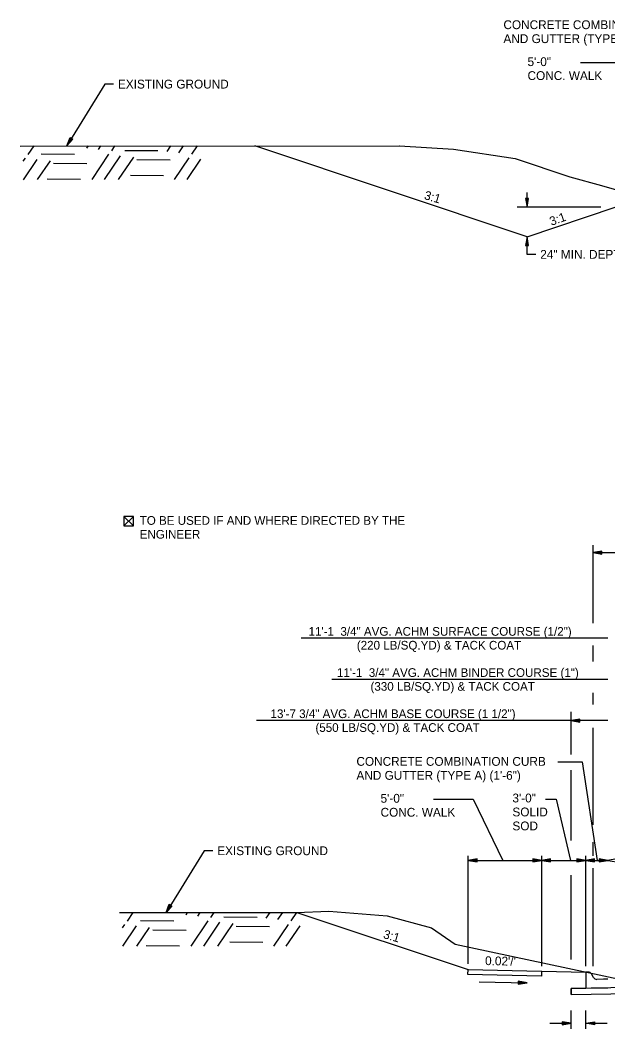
# Model space of a CAD drawing. Extents: x 1001270 to 1003428, y 1840152 to 1842912.
# Drawn here: x 1001270.4 to 1001310.4, y 1842116.6 to 1842185.2 of the extents above; entities that cross this region are included whole.
import ezdxf

# ---------------------------------------------------------------- set-up
doc = ezdxf.new("R2010")
doc.units = 0
for name, color, linetype in [('10', 7, 'Continuous'), ('19', 7, 'Continuous'), ('20', 7, 'Continuous'), ('8', 7, 'Continuous'), ('Default', 7, 'Continuous')]:
    doc.layers.add(name, color=color, linetype=linetype)

# ---------------------------------------------------------------- blocks, each defined once
blk = doc.blocks.new('TM')
at = {"layer": '8'}
for p, q in [((-120.309, 21.181), (-119.787, -20.829)), ((0, 0), (-120.309, 21.181)), ((-31.382, 2.945), (-120.176, 10.512)), ((-119.787, -20.829), (0, 0)), ((-119.911, -10.826), (-31.307, -3.057))]:
    blk.add_line(p, q, dxfattribs=at)

msp = doc.modelspace()

# ---------------------------------------------------------------- linework, layer by layer
at = {"layer": '10'}
for p, q in [((1001277.481, 1842151.422), (1001278.123, 1842150.781)), ((1001278.123, 1842151.422), (1001277.481, 1842150.781)), ((1001277.863, 1842150.781), (1001277.874, 1842150.781))]:
    msp.add_line(p, q, dxfattribs=at)
msp.add_lwpolyline([(1001277.874, 1842150.781), (1001278.123, 1842150.781), (1001278.123, 1842151.422), (1001277.481, 1842151.422), (1001277.481, 1842150.781), (1001277.863, 1842150.781)], dxfattribs=at)
at = {"layer": '19'}
for p, q in [((1001308.535, 1842182.289), (1001311.246, 1842182.289)), ((1001273.593, 1842176.626), (1001273.817, 1842177.193)), ((1001273.667, 1842176.767), (1001273.86, 1842177.16)), ((1001273.817, 1842177.193), (1001273.995, 1842177.083)), ((1001270.971, 1842176.041), (1001271.363, 1842176.624)), ((1001273.995, 1842177.083), (1001273.593, 1842176.626)), ((1001273.954, 1842177.104), (1001273.69, 1842176.755)), ((1001274.957, 1842176.475), (1001275.062, 1842176.625)), ((1001275.751, 1842176.383), (1001275.917, 1842176.627)), ((1001276.647, 1842176.291), (1001276.872, 1842176.63)), ((1001280.411, 1842176.235), (1001280.673, 1842176.631)), ((1001281.205, 1842176.144), (1001281.537, 1842176.632)), ((1001282.101, 1842176.051), (1001282.482, 1842176.625)), ((1001304.904, 1842170.448), (1001286.377, 1842176.624)), ((1001270.632, 1842175.573), (1001270.785, 1842175.798)), ((1001271.86, 1842176.08), (1001274.12, 1842176.059)), ((1001275.309, 1842174.328), (1001276.461, 1842176.049)), ((1001276.163, 1842174.33), (1001277.256, 1842175.957)), ((1001277.119, 1842174.332), (1001278.151, 1842175.865)), ((1001277.534, 1842176.32), (1001279.795, 1842176.309)), ((1001280.919, 1842174.333), (1001281.915, 1842175.809)), ((1001270.654, 1842174.324), (1001271.58, 1842175.707)), ((1001271.609, 1842174.326), (1001272.475, 1842175.615)), ((1001272.7, 1842175.451), (1001274.96, 1842175.429)), ((1001278.364, 1842175.692), (1001280.635, 1842175.68)), ((1001281.773, 1842174.336), (1001282.71, 1842175.717)), ((1001277.922, 1842174.622), (1001280.182, 1842174.6)), ((1001272.247, 1842174.371), (1001274.518, 1842174.359)), ((1001305.009, 1842173.048), (1001304.799, 1842173.048)), ((1001304.799, 1842173.048), (1001304.904, 1842172.448)), ((1001304.849, 1842173.048), (1001304.889, 1842172.608)), ((1001304.904, 1842172.448), (1001304.904, 1842173.451)), ((1001304.904, 1842172.448), (1001305.009, 1842173.048)), ((1001304.919, 1842172.608), (1001304.954, 1842173.048)), ((1001309.914, 1842172.448), (1001304.234, 1842172.448)), ((1001304.904, 1842170.448), (1001310.902, 1842172.448)), ((1001304.904, 1842170.448), (1001304.799, 1842169.848)), ((1001305.009, 1842169.848), (1001304.904, 1842170.448)), ((1001304.904, 1842169.242), (1001304.904, 1842170.448)), ((1001304.799, 1842169.848), (1001305.009, 1842169.848)), ((1001304.889, 1842170.288), (1001304.854, 1842169.848)), ((1001304.959, 1842169.848), (1001304.919, 1842170.288)), ((1001305.504, 1842169.242), (1001304.904, 1842169.242)), ((1001309.401, 1842144.149), (1001309.401, 1842149.464)), ((1001310.001, 1842149.066), (1001309.401, 1842148.961)), ((1001310.001, 1842148.856), (1001310.001, 1842149.066)), ((1001309.401, 1842148.961), (1001375.401, 1842148.961)), ((1001309.401, 1842148.961), (1001310.001, 1842148.856)), ((1001310.001, 1842149.011), (1001309.561, 1842148.976)), ((1001309.561, 1842148.946), (1001310.001, 1842148.906)), ((1001310.407, 1842143.127), (1001289.535, 1842143.127)), ((1001309.401, 1842141.54), (1001309.401, 1842142.648)), ((1001310.401, 1842140.328), (1001291.623, 1842140.328)), ((1001309.401, 1842138.634), (1001309.401, 1842139.415)), ((1001307.901, 1842135.23), (1001307.901, 1842138.128)), ((1001310.401, 1842137.528), (1001286.495, 1842137.528)), ((1001308.501, 1842137.633), (1001307.901, 1842137.528)), ((1001307.901, 1842137.528), (1001308.501, 1842137.423)), ((1001308.501, 1842137.578), (1001308.061, 1842137.543)), ((1001308.061, 1842137.513), (1001308.501, 1842137.473)), ((1001308.501, 1842137.423), (1001308.501, 1842137.633)), ((1001309.401, 1842130.45), (1001309.401, 1842137.03)), ((1001306.992, 1842134.716), (1001308.66, 1842134.716)), ((1001308.66, 1842134.716), (1001309.675, 1842128.024)), ((1001307.901, 1842129.372), (1001307.901, 1842134.158)), ((1001298.536, 1842132.181), (1001301.247, 1842132.181)), ((1001301.247, 1842132.181), (1001303.26, 1842128.01)), ((1001306.152, 1842132.181), (1001306.896, 1842132.181)), ((1001306.896, 1842132.181), (1001307.852, 1842128.024)), ((1001309.401, 1842128.335), (1001309.401, 1842129.264)), ((1001300.901, 1842120.976), (1001300.901, 1842128.324)), ((1001301.501, 1842128.129), (1001300.901, 1842128.024)), ((1001300.901, 1842128.024), (1001310.401, 1842128.024)), ((1001300.901, 1842128.024), (1001301.501, 1842127.919)), ((1001301.501, 1842128.074), (1001301.061, 1842128.039)), ((1001301.061, 1842128.009), (1001301.501, 1842127.969)), ((1001301.501, 1842127.919), (1001301.501, 1842128.129)), ((1001305.301, 1842128.129), (1001305.301, 1842127.919)), ((1001305.901, 1842128.024), (1001305.301, 1842128.129)), ((1001305.741, 1842128.039), (1001305.301, 1842128.074)), ((1001305.301, 1842127.919), (1001305.901, 1842128.024)), ((1001305.301, 1842127.969), (1001305.741, 1842128.009)), ((1001305.901, 1842120.823), (1001305.901, 1842128.324)), ((1001306.501, 1842128.129), (1001305.901, 1842128.024)), ((1001305.901, 1842128.024), (1001306.501, 1842127.919)), ((1001306.501, 1842128.074), (1001306.061, 1842128.039)), ((1001306.061, 1842128.009), (1001306.501, 1842127.969)), ((1001306.501, 1842127.919), (1001306.501, 1842128.129)), ((1001308.301, 1842128.129), (1001308.301, 1842127.919)), ((1001308.901, 1842128.024), (1001308.301, 1842128.129)), ((1001308.741, 1842128.039), (1001308.301, 1842128.074)), ((1001308.301, 1842127.919), (1001308.901, 1842128.024)), ((1001308.301, 1842127.969), (1001308.741, 1842128.009)), ((1001308.901, 1842120.823), (1001308.901, 1842128.324)), ((1001309.501, 1842128.129), (1001308.901, 1842128.024)), ((1001308.901, 1842128.024), (1001309.501, 1842127.919)), ((1001309.501, 1842128.074), (1001309.061, 1842128.039)), ((1001309.061, 1842128.009), (1001309.501, 1842127.969)), ((1001309.501, 1842127.919), (1001309.501, 1842128.129)), ((1001309.801, 1842128.129), (1001309.801, 1842127.919)), ((1001310.401, 1842128.024), (1001309.801, 1842128.129)), ((1001310.241, 1842128.039), (1001309.801, 1842128.074)), ((1001309.801, 1842127.919), (1001310.401, 1842128.024)), ((1001309.801, 1842127.969), (1001310.241, 1842128.009)), ((1001311.001, 1842128.129), (1001310.401, 1842128.024)), ((1001310.401, 1842128.024), (1001311.001, 1842127.919)), ((1001309.401, 1842120.826), (1001309.401, 1842127.504)), ((1001307.901, 1842121.289), (1001307.901, 1842127.028)), ((1001280.345, 1842124.48), (1001280.568, 1842125.047)), ((1001280.419, 1842124.621), (1001280.611, 1842125.015)), ((1001280.568, 1842125.047), (1001280.746, 1842124.937)), ((1001277.723, 1842123.895), (1001278.114, 1842124.478)), ((1001280.746, 1842124.937), (1001280.345, 1842124.48)), ((1001280.705, 1842124.959), (1001280.441, 1842124.61)), ((1001281.708, 1842124.329), (1001281.814, 1842124.479)), ((1001282.503, 1842124.237), (1001282.669, 1842124.482)), ((1001283.398, 1842124.145), (1001283.624, 1842124.484)), ((1001287.162, 1842124.09), (1001287.424, 1842124.485)), ((1001287.957, 1842123.998), (1001288.289, 1842124.486)), ((1001288.852, 1842123.906), (1001289.233, 1842124.48)), ((1001277.383, 1842123.427), (1001277.537, 1842123.653)), ((1001278.611, 1842123.934), (1001280.871, 1842123.913)), ((1001282.06, 1842122.182), (1001283.212, 1842123.903)), ((1001282.915, 1842122.185), (1001284.007, 1842123.811)), ((1001283.87, 1842122.187), (1001284.902, 1842123.719)), ((1001284.286, 1842124.175), (1001286.546, 1842124.163)), ((1001287.67, 1842122.188), (1001288.666, 1842123.664)), ((1001277.405, 1842122.179), (1001278.332, 1842123.561)), ((1001278.36, 1842122.181), (1001279.227, 1842123.469)), ((1001279.451, 1842123.305), (1001281.711, 1842123.284)), ((1001285.116, 1842123.546), (1001287.386, 1842123.534)), ((1001288.525, 1842122.19), (1001289.461, 1842123.572)), ((1001284.674, 1842122.476), (1001286.933, 1842122.455)), ((1001278.998, 1842122.226), (1001281.269, 1842122.213)), ((1001300.887, 1842120.258), (1001300.901, 1842120.591)), ((1001305.886, 1842120.157), (1001300.887, 1842120.258)), ((1001300.901, 1842120.591), (1001305.899, 1842120.49)), ((1001305.899, 1842120.49), (1001305.886, 1842120.157)), ((1001309.067, 1842120.43), (1001308.901, 1842120.43)), ((1001308.901, 1842120.43), (1001308.901, 1842120.097)), ((1001309.429, 1842120.055), (1001309.283, 1842120.306)), ((1001305.886, 1842120.157), (1001305.886, 1842120.157)), ((1001308.901, 1842120.097), (1001308.901, 1842119.915)), ((1001308.901, 1842119.915), (1001308.901, 1842119.322)), ((1001310.116, 1842119.939), (1001309.651, 1842119.93)), ((1001310.401, 1842119.945), (1001310.116, 1842119.939)), ((1001310.116, 1842119.939), (1001310.116, 1842119.939)), ((1001310.116, 1842119.939), (1001310.116, 1842119.939)), ((1001316.396, 1842119.482), (1001307.901, 1842119.302)), ((1001307.901, 1842119.302), (1001308.901, 1842119.322)), ((1001307.901, 1842118.895), (1001307.901, 1842119.302)), ((1001307.901, 1842119.302), (1001307.901, 1842118.895)), ((1001307.901, 1842118.895), (1001323.401, 1842119.205)), ((1001307.901, 1842118.895), (1001323.401, 1842119.205)), ((1001308.901, 1842119.322), (1001310.401, 1842119.353)), ((1001307.901, 1842116.566), (1001307.901, 1842117.804)), ((1001308.901, 1842116.566), (1001308.901, 1842117.804)), ((1001306.452, 1842116.944), (1001307.901, 1842116.944)), ((1001306.452, 1842116.944), (1001307.901, 1842116.944)), ((1001307.301, 1842117.049), (1001307.301, 1842116.839)), ((1001307.901, 1842116.944), (1001307.301, 1842117.049)), ((1001307.301, 1842117.049), (1001307.301, 1842116.839)), ((1001307.901, 1842116.944), (1001307.301, 1842117.049)), ((1001307.741, 1842116.959), (1001307.301, 1842116.994)), ((1001307.741, 1842116.959), (1001307.301, 1842116.994)), ((1001307.301, 1842116.839), (1001307.901, 1842116.944)), ((1001307.301, 1842116.839), (1001307.901, 1842116.944)), ((1001307.301, 1842116.889), (1001307.741, 1842116.929)), ((1001307.301, 1842116.889), (1001307.741, 1842116.929)), ((1001308.901, 1842116.944), (1001309.501, 1842117.049)), ((1001308.901, 1842116.944), (1001309.501, 1842117.049)), ((1001309.501, 1842116.839), (1001308.901, 1842116.944)), ((1001308.901, 1842116.944), (1001310.349, 1842116.944)), ((1001309.501, 1842116.839), (1001308.901, 1842116.944)), ((1001308.901, 1842116.944), (1001310.349, 1842116.944)), ((1001309.061, 1842116.959), (1001309.501, 1842116.994)), ((1001309.061, 1842116.959), (1001309.501, 1842116.994)), ((1001309.501, 1842116.889), (1001309.061, 1842116.929)), ((1001309.501, 1842116.889), (1001309.061, 1842116.929)), ((1001309.501, 1842117.049), (1001309.501, 1842116.839)), ((1001309.501, 1842117.049), (1001309.501, 1842116.839))]:
    msp.add_line(p, q, dxfattribs=at)
for points in [[(1001276.776, 1842180.825), (1001276.176, 1842180.825), (1001273.593, 1842176.626)], [(1001270.422, 1842176.607), (1001296.261, 1842176.634)], [(1001296.221, 1842176.634), (1001299.91, 1842176.411), (1001304.093, 1842175.76), (1001307.815, 1842174.527), (1001309.967, 1842173.924), (1001321.546, 1842170.597), (1001323.958, 1842170.518), (1001338.494, 1842171.096), (1001350.395, 1842170.749), (1001353.487, 1842170.546), (1001356.033, 1842170.375), (1001363.821, 1842168.673), (1001370.478, 1842168.355), (1001375.271, 1842167.658), (1001378.188, 1842167.647)], [(1001283.528, 1842128.679), (1001282.928, 1842128.679), (1001280.345, 1842124.48)], [(1001277.172, 1842124.478), (1001289.226, 1842124.48)], [(1001289.226, 1842124.48), (1001291.425, 1842124.57), (1001295.382, 1842124.242), (1001298.395, 1842123.433), (1001300.026, 1842122.329), (1001313.958, 1842119.365), (1001323.401, 1842119.667), (1001331.735, 1842119.949), (1001335.313, 1842119.985), (1001341.621, 1842119.885), (1001348.336, 1842119.792), (1001353.401, 1842119.705), (1001356.081, 1842119.644)], [(1001289.233, 1842124.48), (1001300.901, 1842120.591), (1001308.901, 1842120.43)]]:
    msp.add_lwpolyline(points, dxfattribs=at)
for centre, start, end in [((1001309.067, 1842120.18), 30.1619, 90), ((1001309.646, 1842120.18), 210.16348, 271.14576)]:
    msp.add_arc(centre, 0.25, start, end, dxfattribs=at)
at = {"layer": '20'}
msp.add_line((1001301.64, 1842119.758), (1001304.91, 1842119.693), dxfattribs=at)

# ---------------------------------------------------------------- block references
at = {"layer": '19', "xscale": 0.005006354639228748, "yscale": 0.005006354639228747, "rotation": -1.131077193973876}
msp.add_blockref('TM', (1001304.91, 1842119.69), dxfattribs=at)

# ---------------------------------------------------------------- texts
at = {"layer": '19'}
for s, rotation, p in [('CONCRETE COMBINATION CURB', 360, (1001303.298, 1842184.565)), ('AND GUTTER (TYPE A) (1\'-6")', 360, (1001303.298, 1842183.615)), ('5\'-0"', 360, (1001304.939, 1842182.052)), ('CONC. WALK', 360, (1001304.939, 1842181.102)), ('3:1', 343.76133, (1001297.859, 1842173.012)), ('3:1', 19.50574, (1001306.56, 1842171.182)), ('CONCRETE COMBINATION CURB', 360, (1001293.298, 1842134.457)), ('AND GUTTER (TYPE A) (1\'-6")', 360, (1001293.298, 1842133.507)), ('3\'-0"', 360, (1001303.91, 1842131.966)), ('5\'-0"', 360, (1001294.94, 1842131.945)), ('CONC. WALK', 360, (1001294.94, 1842130.995)), ('SOLID ', 360, (1001303.91, 1842131.016)), ('SOD', 360, (1001303.91, 1842130.066)), ('3:1', 343.76133, (1001295.077, 1842122.747)), ("0.02'/'", 358.84117, (1001302.045, 1842120.902))]:
    msp.add_text(s, height=0.6, rotation=rotation, dxfattribs=at).set_placement(p)
for s, height, p in [('EXISTING GROUND', 0.6, (1001277.076, 1842180.525)), ('24" MIN. DEPTH', 0.6, (1001305.804, 1842168.942)), ('11\'-1  3/4" AVG. ACHM SURFACE COURSE (1/2")', 0.59001, (1001290.042, 1842143.303)), ('(220 LB/SQ.YD) & TACK COAT', 0.59001, (1001293.324, 1842142.363)), ('11\'-1  3/4" AVG. ACHM BINDER COURSE (1")', 0.59001, (1001291.972, 1842140.503)), ('(330 LB/SQ.YD) & TACK COAT', 0.59001, (1001294.255, 1842139.563)), ('13\'-7 3/4" AVG. ACHM BASE COURSE (1 1/2")', 0.59001, (1001287.454, 1842137.703)), ('(550 LB/SQ.YD) & TACK COAT', 0.59001, (1001290.508, 1842136.763)), ('EXISTING GROUND', 0.6, (1001283.828, 1842128.379))]:
    msp.add_text(s, height=height, dxfattribs=at).set_placement(p)
at = {"layer": 'Default'}
for s, height, p in [('TO BE USED IF AND WHERE DIRECTED BY THE ', 0.59001, (1001278.554, 1842150.849)), ('ENGINEER', 0.59, (1001278.554, 1842149.909))]:
    msp.add_text(s, height=height, rotation=359.99538, dxfattribs=at).set_placement(p)

doc.saveas('drawing.dxf')
